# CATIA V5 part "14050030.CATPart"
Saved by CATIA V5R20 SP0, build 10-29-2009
Part number: 14050030
Definition: NONE
Nomenclature: 14050030
Source: Unknown
Description: 14050030
Bounding box of the stored display mesh (mm): x -15 to 60, y -39 to 29.1, z -29.1 to 29.1
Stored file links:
  C:\Users\Utente\Desktop\IO LAVORO\3D X SITO CF\X SITO\PLASTICA\RF2\14050030.CATPart
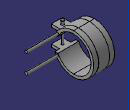
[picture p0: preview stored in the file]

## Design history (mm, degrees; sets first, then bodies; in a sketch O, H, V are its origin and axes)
Body1 "14050030" (main body)
  Solid1: solid without history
